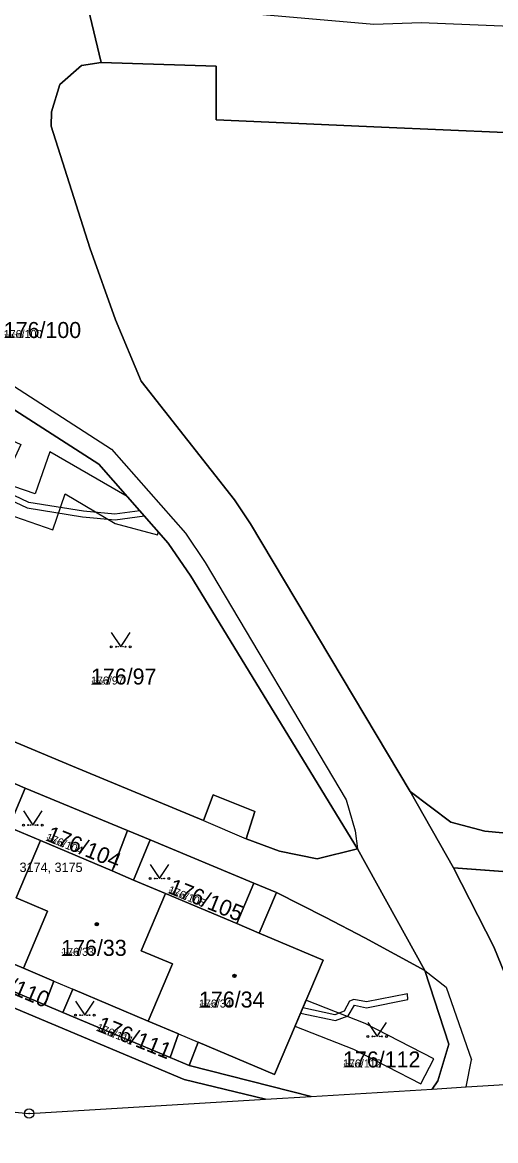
# Model space of a CAD drawing. Extents: x -759873 to -758487, y -975024 to -973516.
# Drawn here: x -759712.9 to -759662.7, y -974999.9 to -974881.1 of the extents above; entities that cross this region are included whole.
import ezdxf

# ---------------------------------------------------------------- set-up
doc = ezdxf.new("R2010")
doc.units = 0
for name, color, linetype in [('KAT_01_hranice KU', 7, 'Continuous'), ('KAT_02_hranice parcel', 7, 'Continuous'), ('KAT_03_1000_st čísla parcelní', 7, 'Continuous'), ('KAT_03_1000_čísla parcelní', 7, 'Continuous'), ('KAT_03_1000_čísla popisná', 7, 'Continuous'), ('KAT_03_250_st čísla parcelní', 7, 'Continuous'), ('KAT_03_250_čísla parcelní', 7, 'Continuous'), ('KAT_03_500_st čísla parcelní', 7, 'Continuous'), ('KAT_03_500_čísla parcelní', 7, 'Continuous'), ('KAT_04_vnitřní kresba', 7, 'Continuous'), ('KAT_05_1000_značky kultur', 7, 'Continuous'), ('KAT_05_250_značky kultur', 7, 'Continuous'), ('KAT_05_500_značky kultur', 7, 'Continuous'), ('KAT_07_1000_značky budov', 7, 'Continuous'), ('KAT_07_250_značky budov', 7, 'Continuous'), ('KAT_07_500_značky budov', 7, 'Continuous'), ('KAT_10_věcná břemena', 7, 'Continuous'), ('KAT_11_značky bodu BP', 7, 'Continuous'), ('KAT_14_plocha_budovy', 7, 'Continuous'), ('KAT_14_plocha_pozemek', 7, 'Continuous')]:
    doc.layers.add(name, color=color, linetype=linetype)

msp = doc.modelspace()

# ---------------------------------------------------------------- linework, layer by layer
at = {"layer": 'KAT_01_hranice KU'}
msp.add_lwpolyline([(-759719.75, -974996.3), (-759712.2, -974997), (-759687.1, -974995.48), (-759682.26, -974995.18), (-759669.4, -974994.4), (-759665.8, -974994.18), (-759657.02, -974993.65)], dxfattribs=at)
at = {"layer": 'KAT_02_hranice parcel'}
for p, q in [((-759712.6, -974962.44), (-759715, -974961.43)), ((-759712.6, -974962.44), (-759701.74, -974966.94)), ((-759667.12, -974970.91), (-759671.72, -974962.82)), ((-759699.33, -974967.95), (-759701.74, -974966.94)), ((-759699.33, -974967.95), (-759688.34, -974972.53)), ((-759670.18, -974981.81), (-759677.32, -974968.89)), ((-759667.12, -974970.91), (-759656.59, -974971.69)), ((-759685.92, -974973.55), (-759688.34, -974972.53)), ((-759710.53, -974985.47), (-759721.86, -974980.66)), ((-759710.53, -974985.47), (-759708.61, -974986.28)), ((-759697.21, -974991.07), (-759708.61, -974986.28)), ((-759697.21, -974991.07), (-759695.19, -974991.9)), ((-759682.26, -974995.18), (-759695.19, -974991.9)), ((-759682.26, -974995.18), (-759669.4, -974994.4)), ((-759712.2, -974997), (-759687.1, -974995.48)), ((-759687.1, -974995.48), (-759682.26, -974995.18)), ((-759719.75, -974996.3), (-759712.2, -974997))]:
    msp.add_line(p, q, dxfattribs=at)
for points in [[(-759704.55, -974885.39), (-759706.33, -974877.97), (-759706.64, -974876.66)], [(-759671.72, -974962.82), (-759688.7, -974934.38), (-759690.39, -974931.84), (-759700.31, -974919.23), (-759703.03, -974912.74), (-759705.76, -974905.09), (-759709.86, -974892.15), (-759709.83, -974890.64), (-759708.93, -974887.73), (-759706.65, -974885.73), (-759704.55, -974885.39)], [(-759704.55, -974885.39), (-759692.32, -974885.8), (-759692.32, -974891.5), (-759674.78, -974892.27), (-759648.58, -974893.39), (-759620.34, -974894.6), (-759598.34, -974895.81)], [(-759677.32, -974968.89), (-759695.02, -974939.95), (-759697.42, -974936.43), (-759704.8, -974928.04), (-759718.22, -974919.45)], [(-759719.7, -974955.06), (-759707.59, -974960.11), (-759693.68, -974965.9), (-759692.65, -974963.17), (-759688.22, -974964.93), (-759689.15, -974967.84), (-759685.61, -974969.13), (-759681.6, -974969.96), (-759677.32, -974968.89)], [(-759770.81, -974966.03), (-759769.24, -974962.19), (-759758.63, -974966.73), (-759760.18, -974970.6), (-759752.01, -974974.08), (-759750.27, -974970.29), (-759722.49, -974982.07), (-759724.08, -974985.84), (-759715.79, -974989.44), (-759714.25, -974985.59), (-759695.75, -974993.4), (-759687.1, -974995.48)], [(-759710.99, -974968.02), (-759714.34, -974966.61), (-759712.6, -974962.44)], [(-759604.4, -974972.46), (-759624.01, -974970.63), (-759644.32, -974968.81), (-759663.8, -974967.02), (-759667.42, -974966.06), (-759671.72, -974962.82)], [(-759701.74, -974966.94), (-759703.37, -974971.25), (-759710.99, -974968.02)], [(-759712.81, -974981.58), (-759710.24, -974975.5), (-759713.56, -974974.1), (-759710.99, -974968.02)], [(-759697.72, -974973.63), (-759701.1, -974972.21), (-759699.33, -974967.95)], [(-759657.02, -974993.65), (-759662.86, -974979.29), (-759667.12, -974970.91)], [(-759688.34, -974972.53), (-759690.14, -974976.84), (-759697.72, -974973.63)], [(-759699.55, -974987.19), (-759696.98, -974981.11), (-759700.29, -974979.71), (-759697.72, -974973.63)], [(-759695.19, -974991.9), (-759694.26, -974989.42), (-759686.15, -974992.85), (-759680.99, -974980.71), (-759687.76, -974977.85), (-759685.92, -974973.55)], [(-759685.92, -974973.55), (-759680.77, -974976.14), (-759676.56, -974978.33), (-759670.18, -974981.81)], [(-759721.86, -974980.66), (-759720.74, -974978.23), (-759712.81, -974981.58)], [(-759712.81, -974981.58), (-759709.59, -974982.94), (-759710.53, -974985.47)], [(-759670.18, -974981.81), (-759667.63, -974989.62), (-759668.8, -974993.53), (-759669.4, -974994.4)], [(-759708.61, -974986.28), (-759707.54, -974983.81), (-759699.55, -974987.19)], [(-759699.55, -974987.19), (-759696.34, -974988.54), (-759697.21, -974991.07)], [(-759669.4, -974994.4), (-759665.8, -974994.18), (-759657.02, -974993.65)]]:
    msp.add_lwpolyline(points, dxfattribs=at)
at = {"layer": 'KAT_04_vnitřní kresba'}
for p, q in [((-759698.79, -974879.31), (-759675.58, -974881.34)), ((-759675.58, -974881.34), (-759670.56, -974881.16)), ((-759670.56, -974881.16), (-759661.09, -974881.56)), ((-759717.15, -974917.64), (-759703.44, -974926.45)), ((-759703.44, -974926.45), (-759695.59, -974935.37)), ((-759695.59, -974935.37), (-759693.52, -974938.49)), ((-759693.52, -974938.49), (-759678.52, -974963.71)), ((-759678.52, -974963.71), (-759677.57, -974966.99)), ((-759693.68, -974965.9), (-759689.15, -974967.84)), ((-759677.57, -974966.99), (-759677.32, -974968.89)), ((-759703.37, -974971.25), (-759701.1, -974972.21)), ((-759690.14, -974976.84), (-759687.76, -974977.85)), ((-759709.59, -974982.94), (-759707.54, -974983.81)), ((-759670.18, -974981.81), (-759667.9, -974983.59)), ((-759667.9, -974983.59), (-759665.23, -974991.3)), ((-759696.34, -974988.54), (-759694.26, -974989.42)), ((-759665.8, -974994.18), (-759665.23, -974991.3))]:
    msp.add_line(p, q, dxfattribs=at)
at = {"layer": 'KAT_05_1000_značky kultur'}
for points in [[(-759703.47, -974945.94), (-759702.47, -974947.44), (-759701.47, -974945.94)], [(-759712.8, -974964.88), (-759711.8, -974966.38), (-759710.8, -974964.88)], [(-759699.36, -974970.55), (-759698.36, -974972.05), (-759697.36, -974970.55)], [(-759707.29, -974985.06), (-759706.29, -974986.56), (-759705.29, -974985.06)], [(-759676.24, -974987.32), (-759675.24, -974988.82), (-759674.24, -974987.32)]]:
    msp.add_lwpolyline(points, dxfattribs=at)
for centre in [(-759703.47, -974947.44), (-759701.47, -974947.44), (-759712.8, -974966.38), (-759710.8, -974966.38), (-759699.36, -974972.05), (-759697.36, -974972.05), (-759707.29, -974986.56), (-759705.29, -974986.56), (-759676.24, -974988.82), (-759674.24, -974988.82)]:
    msp.add_circle(centre, 0.1, dxfattribs=at)
at = {"layer": 'KAT_05_250_značky kultur'}
for points in [[(-759702.72, -974947.06), (-759702.47, -974947.44), (-759702.22, -974947.06)], [(-759712.05, -974966), (-759711.8, -974966.38), (-759711.55, -974966)], [(-759698.61, -974971.67), (-759698.36, -974972.05), (-759698.11, -974971.67)], [(-759706.54, -974986.18), (-759706.29, -974986.56), (-759706.04, -974986.18)], [(-759675.49, -974988.44), (-759675.24, -974988.82), (-759674.99, -974988.44)]]:
    msp.add_lwpolyline(points, dxfattribs=at)
for centre in [(-759702.72, -974947.44), (-759702.22, -974947.44), (-759712.05, -974966.38), (-759711.55, -974966.38), (-759698.61, -974972.05), (-759698.11, -974972.05), (-759706.54, -974986.56), (-759706.04, -974986.56), (-759675.49, -974988.82), (-759674.99, -974988.82)]:
    msp.add_circle(centre, 0.025, dxfattribs=at)
at = {"layer": 'KAT_05_500_značky kultur'}
for points in [[(-759702.97, -974946.69), (-759702.47, -974947.44), (-759701.97, -974946.69)], [(-759712.3, -974965.63), (-759711.8, -974966.38), (-759711.3, -974965.63)], [(-759698.86, -974971.3), (-759698.36, -974972.05), (-759697.86, -974971.3)], [(-759706.79, -974985.81), (-759706.29, -974986.56), (-759705.79, -974985.81)], [(-759675.74, -974988.07), (-759675.24, -974988.82), (-759674.74, -974988.07)]]:
    msp.add_lwpolyline(points, dxfattribs=at)
for centre in [(-759702.97, -974947.44), (-759701.97, -974947.44), (-759712.3, -974966.38), (-759711.3, -974966.38), (-759698.86, -974972.05), (-759697.86, -974972.05), (-759706.79, -974986.56), (-759705.79, -974986.56), (-759675.74, -974988.82), (-759674.74, -974988.82)]:
    msp.add_circle(centre, 0.05, dxfattribs=at)
at = {"layer": 'KAT_07_1000_značky budov'}
for centre in [(-759705.02, -974976.9), (-759690.39, -974982.39)]:
    msp.add_circle(centre, 0.175, dxfattribs=at)
at = {"layer": 'KAT_07_250_značky budov'}
for centre in [(-759705.01, -974976.9), (-759690.38, -974982.39)]:
    msp.add_circle(centre, 0.0437, dxfattribs=at)
at = {"layer": 'KAT_07_500_značky budov'}
for centre in [(-759705.01, -974976.9), (-759690.38, -974982.39)]:
    msp.add_circle(centre, 0.0875, dxfattribs=at)
at = {"layer": 'KAT_10_věcná břemena'}
for points in [[(-759714.97, -974930.02), (-759716.24, -974932.76), (-759709.68, -974935.03), (-759708.37, -974931.19), (-759703.05, -974934.36), (-759698.55, -974935.54), (-759698.47, -974935.23), (-759701.78, -974931.48), (-759710.01, -974926.73), (-759711.54, -974931.21)], [(-759715.28, -974930.69), (-759715.53, -974931.24), (-759712.4, -974932.69), (-759706.52, -974933.65), (-759703.06, -974933.96), (-759699.96, -974933.54), (-759700.43, -974933), (-759703.08, -974933.36), (-759706.44, -974933.05), (-759712.22, -974932.11)], [(-759682.8, -974984.96), (-759683.97, -974987.72), (-759677.75, -974990.18), (-759670.6, -974993.85), (-759669.23, -974991.18), (-759676.53, -974987.44)], [(-759683.15, -974985.78), (-759683.39, -974986.35), (-759679.66, -974987.14), (-759678.33, -974986.62), (-759677.65, -974985.5), (-759676.36, -974985.78), (-759672, -974984.91), (-759672.03, -974984.31), (-759676.36, -974985.16), (-759677.71, -974984.88), (-759678.17, -974985.06), (-759678.75, -974986.14), (-759679.72, -974986.52)]]:
    msp.add_lwpolyline(points, close=True, dxfattribs=at)
at = {"layer": 'KAT_11_značky bodu BP'}
for radius in [0.5, 0.0303]:
    msp.add_circle((-759712.2, -974997), radius, dxfattribs=at)
at = {"layer": 'KAT_14_plocha_budovy'}
msp.add_lwpolyline([(-759720.74, -974978.23), (-759712.81, -974981.58), (-759709.59, -974982.94), (-759707.54, -974983.81), (-759699.55, -974987.19), (-759696.34, -974988.54), (-759694.26, -974989.42), (-759686.15, -974992.85), (-759680.99, -974980.71), (-759687.76, -974977.85), (-759690.14, -974976.84), (-759697.72, -974973.63), (-759701.1, -974972.21), (-759703.37, -974971.25), (-759710.99, -974968.02), (-759714.34, -974966.61), (-759716.67, -974965.62), (-759724.48, -974962.32), (-759729.62, -974974.47), (-759722.83, -974977.34)], close=True, dxfattribs=at)
at = {"layer": 'KAT_14_plocha_pozemek'}
for points in [[(-759649.68, -974880.37), (-759665.96, -974879.65), (-759668.14, -974879.63), (-759674.76, -974879.81), (-759686.6, -974878.96), (-759688.56, -974878.81), (-759695.86, -974878.31), (-759706.64, -974876.66), (-759706.33, -974877.97), (-759704.55, -974885.39), (-759692.32, -974885.8), (-759692.32, -974891.5), (-759674.78, -974892.27), (-759648.58, -974893.39)], [(-759718.22, -974919.45), (-759704.8, -974928.04), (-759697.42, -974936.43), (-759695.02, -974939.95), (-759677.32, -974968.89), (-759670.18, -974981.81), (-759667.63, -974989.62), (-759668.8, -974993.53), (-759669.4, -974994.4), (-759665.8, -974994.18), (-759657.02, -974993.65), (-759662.86, -974979.29), (-759667.12, -974970.91), (-759671.72, -974962.82), (-759688.7, -974934.38), (-759690.39, -974931.84), (-759700.31, -974919.23), (-759703.03, -974912.74), (-759705.76, -974905.09), (-759709.86, -974892.15), (-759709.83, -974890.64), (-759708.93, -974887.73), (-759706.65, -974885.73), (-759704.55, -974885.39), (-759706.33, -974877.97)], [(-759648.58, -974893.39), (-759674.78, -974892.27), (-759692.32, -974891.5), (-759692.32, -974885.8), (-759704.55, -974885.39), (-759706.65, -974885.73), (-759708.93, -974887.73), (-759709.83, -974890.64), (-759709.86, -974892.15), (-759705.76, -974905.09), (-759703.03, -974912.74), (-759700.31, -974919.23), (-759690.39, -974931.84), (-759688.7, -974934.38), (-759671.72, -974962.82), (-759667.42, -974966.06), (-759663.8, -974967.02), (-759644.32, -974968.81)], [(-759715, -974961.43), (-759712.6, -974962.44), (-759701.74, -974966.94), (-759699.33, -974967.95), (-759688.34, -974972.53), (-759685.92, -974973.55), (-759680.77, -974976.14), (-759676.56, -974978.33), (-759670.18, -974981.81), (-759677.32, -974968.89), (-759681.6, -974969.96), (-759685.61, -974969.13), (-759689.15, -974967.84), (-759688.22, -974964.93), (-759692.65, -974963.17), (-759693.68, -974965.9), (-759707.59, -974960.11), (-759719.7, -974955.06)], [(-759714.25, -974985.59), (-759695.75, -974993.4), (-759687.1, -974995.48), (-759682.26, -974995.18), (-759695.19, -974991.9), (-759697.21, -974991.07), (-759708.61, -974986.28), (-759710.53, -974985.47), (-759721.86, -974980.66)]]:
    msp.add_lwpolyline(points, dxfattribs=at)
for points in [[(-759692.65, -974963.17), (-759688.22, -974964.93), (-759689.15, -974967.84), (-759685.61, -974969.13), (-759681.6, -974969.96), (-759677.32, -974968.89), (-759695.02, -974939.95), (-759697.42, -974936.43), (-759704.8, -974928.04), (-759718.22, -974919.45), (-759719.75, -974922.88), (-759713.09, -974925.97), (-759718.64, -974937.93), (-759726.62, -974934.22), (-759727.76, -974936.66), (-759724.52, -974939.51), (-759718.13, -974944.08), (-759715.89, -974945.28), (-759719.7, -974955.06), (-759707.59, -974960.11), (-759693.68, -974965.9)], [(-759712.81, -974981.58), (-759710.24, -974975.5), (-759713.56, -974974.1), (-759710.99, -974968.02), (-759714.34, -974966.61), (-759712.6, -974962.44), (-759715, -974961.43), (-759716.67, -974965.62), (-759724.48, -974962.32), (-759729.62, -974974.47), (-759722.83, -974977.34), (-759723.78, -974979.84), (-759721.86, -974980.66), (-759720.74, -974978.23)], [(-759727.3, -974996.05), (-759719.75, -974996.3), (-759712.2, -974997), (-759687.1, -974995.48), (-759695.75, -974993.4), (-759714.25, -974985.59), (-759715.79, -974989.44), (-759724.08, -974985.84), (-759722.49, -974982.07), (-759750.27, -974970.29), (-759752.01, -974974.08), (-759760.18, -974970.6), (-759758.63, -974966.73), (-759769.24, -974962.19), (-759770.81, -974966.03), (-759759.81, -974978.29), (-759748.8, -974990.42), (-759740.23, -974999.88)], [(-759712.6, -974962.44), (-759714.34, -974966.61), (-759710.99, -974968.02), (-759703.37, -974971.25), (-759701.74, -974966.94)], [(-759667.42, -974966.06), (-759671.72, -974962.82), (-759667.12, -974970.91), (-759656.59, -974971.69), (-759629.5, -974974.21), (-759625.27, -974974.67), (-759612.46, -974975.88), (-759604.4, -974972.46), (-759624.01, -974970.63), (-759644.32, -974968.81), (-759663.8, -974967.02)], [(-759703.37, -974971.25), (-759710.99, -974968.02), (-759713.56, -974974.1), (-759710.24, -974975.5), (-759712.81, -974981.58), (-759709.59, -974982.94), (-759710.53, -974985.47), (-759708.61, -974986.28), (-759707.54, -974983.81), (-759699.55, -974987.19), (-759696.98, -974981.11), (-759700.29, -974979.71), (-759697.72, -974973.63), (-759701.1, -974972.21), (-759699.33, -974967.95), (-759701.74, -974966.94)], [(-759699.33, -974967.95), (-759701.1, -974972.21), (-759697.72, -974973.63), (-759690.14, -974976.84), (-759688.34, -974972.53)], [(-759652.05, -974993.35), (-759638.94, -974991.86), (-759635.52, -974991.47), (-759631.82, -974990.25), (-759628.8, -974983.86), (-759612.46, -974975.88), (-759625.27, -974974.67), (-759629.5, -974974.21), (-759630.6, -974985.54), (-759657.64, -974983.03), (-759656.59, -974971.69), (-759667.12, -974970.91), (-759662.86, -974979.29), (-759657.02, -974993.65)], [(-759686.15, -974992.85), (-759680.99, -974980.71), (-759687.76, -974977.85), (-759685.92, -974973.55), (-759688.34, -974972.53), (-759690.14, -974976.84), (-759697.72, -974973.63), (-759700.29, -974979.71), (-759696.98, -974981.11), (-759699.55, -974987.19), (-759696.34, -974988.54), (-759697.21, -974991.07), (-759695.19, -974991.9), (-759694.26, -974989.42)], [(-759669.4, -974994.4), (-759668.8, -974993.53), (-759667.63, -974989.62), (-759670.18, -974981.81), (-759676.56, -974978.33), (-759680.77, -974976.14), (-759685.92, -974973.55), (-759687.76, -974977.85), (-759680.99, -974980.71), (-759686.15, -974992.85), (-759694.26, -974989.42), (-759695.19, -974991.9), (-759682.26, -974995.18)], [(-759712.81, -974981.58), (-759720.74, -974978.23), (-759721.86, -974980.66), (-759710.53, -974985.47), (-759709.59, -974982.94)], [(-759699.55, -974987.19), (-759707.54, -974983.81), (-759708.61, -974986.28), (-759697.21, -974991.07), (-759696.34, -974988.54)]]:
    msp.add_lwpolyline(points, close=True, dxfattribs=at)

# ---------------------------------------------------------------- texts
at = {"layer": 'KAT_03_1000_st čísla parcelní'}
for s, p in [('176/33', (-759708.79, -974980.26)), ('176/34', (-759694.16, -974985.75))]:
    msp.add_text(s, height=1.7, dxfattribs=at).set_placement(p)
at = {"layer": 'KAT_03_1000_čísla parcelní'}
for s, p in [('176/100', (-759714.89, -974914.66)), ('176/97', (-759705.63, -974951.45)), ('176/112', (-759678.87, -974992.11))]:
    msp.add_text(s, height=1.7, dxfattribs=at).set_placement(p)
for s, rotation, p in [('176/104', 338, (-759710.5, -974967.99)), ('176/105', 338, (-759697.52, -974973.57)), ('176/110', 337, (-759718.06, -974982.6)), ('176/111', 338, (-759705.13, -974988.19))]:
    msp.add_text(s, height=1.7, rotation=rotation, dxfattribs=at).set_placement(p)
at = {"layer": 'KAT_03_1000_čísla popisná'}
msp.add_text('č.p. 3173, 3174, 3175', height=1, dxfattribs=at).set_placement((-759719.46, -974971.36))
at = {"layer": 'KAT_03_250_st čísla parcelní'}
for s, p in [('176/33', (-759708.79, -974980.26)), ('176/34', (-759694.16, -974985.75))]:
    msp.add_text(s, height=0.425, dxfattribs=at).set_placement(p)
at = {"layer": 'KAT_03_250_čísla parcelní'}
for s, p in [('176/100', (-759714.89, -974914.66)), ('176/97', (-759705.63, -974951.45)), ('176/112', (-759678.87, -974992.11))]:
    msp.add_text(s, height=0.425, dxfattribs=at).set_placement(p)
for s, p in [('176/104', (-759710.5, -974967.99)), ('176/105', (-759697.52, -974973.57)), ('176/111', (-759705.13, -974988.19))]:
    msp.add_text(s, height=0.425, rotation=338, dxfattribs=at).set_placement(p)
at = {"layer": 'KAT_03_500_st čísla parcelní'}
for s, p in [('176/33', (-759708.79, -974980.26)), ('176/34', (-759694.16, -974985.75))]:
    msp.add_text(s, height=0.85, dxfattribs=at).set_placement(p)
at = {"layer": 'KAT_03_500_čísla parcelní'}
for s, p in [('176/100', (-759714.89, -974914.66)), ('176/97', (-759705.63, -974951.45)), ('176/112', (-759678.87, -974992.11))]:
    msp.add_text(s, height=0.85, dxfattribs=at).set_placement(p)
for s, p in [('176/104', (-759710.5, -974967.99)), ('176/105', (-759697.52, -974973.57)), ('176/111', (-759705.13, -974988.19))]:
    msp.add_text(s, height=0.85, rotation=338, dxfattribs=at).set_placement(p)

doc.saveas('drawing.dxf')
